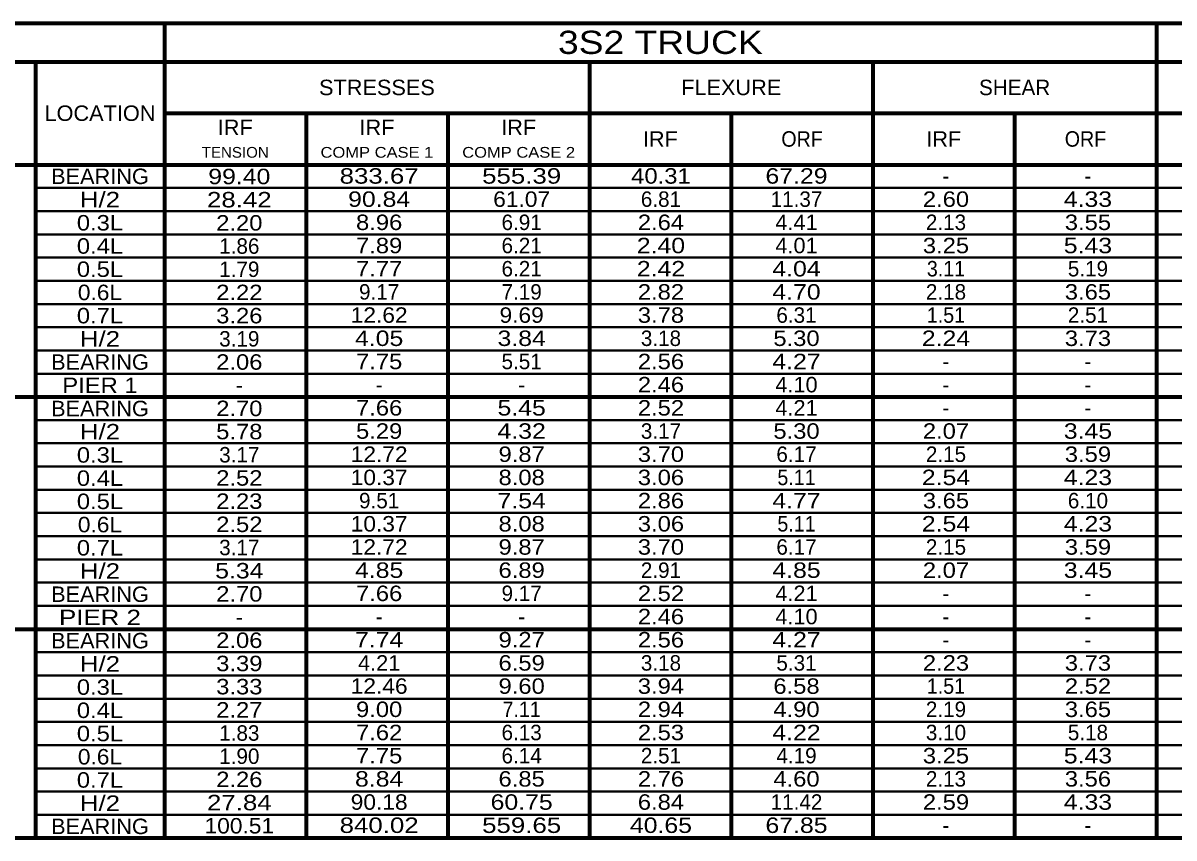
# Model space of a CAD drawing. Extents: x -2055 to -1915, y -81 to 6.
# Drawn here: x -2006.24 to -1961.57, y -66.78 to -35.15 of the extents above; entities that cross this region are included whole.
import ezdxf
from ezdxf.enums import TextEntityAlignment as Align

# ---------------------------------------------------------------- set-up
doc = ezdxf.new("R2010")
doc.units = 0
doc.header["$LTSCALE"] = 0.24
doc.layers.add('1', color=7, linetype='Continuous', lineweight=70)
doc.layers.add('5', color=7, linetype='Continuous', lineweight=40)
doc.layers.add('21', color=7, linetype='Continuous')
doc.layers.add('9', color=7, linetype='Continuous')

msp = doc.modelspace()

# ---------------------------------------------------------------- linework, layer by layer
at = {"layer": '1'}
for p, q in [((-2009.7523, -35.1469), (-1923.7523, -35.1469)), ((-2000.7523, -35.1469), (-2000.7523, -66.7771)), ((-1962.2523, -35.1469), (-1962.2523, -66.7771)), ((-2009.7523, -36.6469), (-1923.7523, -36.6469)), ((-2005.7523, -36.6469), (-2005.7523, -66.7771)), ((-1984.2523, -36.6469), (-1984.2523, -66.7771)), ((-1973.2523, -36.6469), (-1973.2523, -66.7771)), ((-2000.7523, -38.6469), (-1923.7523, -38.6469)), ((-1995.2523, -38.6469), (-1995.2523, -66.7771)), ((-1989.7523, -38.6469), (-1989.7523, -66.7771)), ((-1978.7523, -38.6469), (-1978.7523, -66.7771)), ((-1967.7523, -38.6469), (-1967.7523, -66.7771)), ((-2009.7523, -40.6469), (-1923.7523, -40.6469)), ((-2009.7523, -49.6573), (-1923.7523, -49.6573)), ((-2009.7523, -58.6677), (-1923.7523, -58.6677)), ((-2009.7523, -66.7771), (-1923.7523, -66.7771))]:
    msp.add_line(p, q, dxfattribs=at)
at = {"layer": '5'}
for p, q in [((-2005.7523, -41.5479), (-1923.7523, -41.5479)), ((-2005.7523, -42.449), (-1923.7523, -42.449)), ((-2005.7523, -43.35), (-1923.7523, -43.35)), ((-2005.7523, -44.2511), (-1923.7523, -44.2511)), ((-2005.7523, -45.1521), (-1923.7523, -45.1521)), ((-2005.7523, -46.0532), (-1923.7523, -46.0532)), ((-2005.7523, -46.9542), (-1923.7523, -46.9542)), ((-2005.7523, -47.8552), (-1923.7523, -47.8552)), ((-2005.7523, -48.7563), (-1923.7523, -48.7563)), ((-2005.7523, -50.5583), (-1923.7523, -50.5583)), ((-2005.7523, -51.4594), (-1923.7523, -51.4594)), ((-2005.7523, -52.3604), (-1923.7523, -52.3604)), ((-2005.7523, -53.2615), (-1923.7523, -53.2615)), ((-2005.7523, -54.1625), (-1923.7523, -54.1625)), ((-2005.7523, -55.0636), (-1923.7523, -55.0636)), ((-2005.7523, -55.9646), (-1923.7523, -55.9646)), ((-2005.7523, -56.8657), (-1923.7523, -56.8657)), ((-2005.7523, -57.7667), (-1923.7523, -57.7667)), ((-2005.7523, -59.5688), (-1923.7523, -59.5688)), ((-2005.7523, -60.4698), (-1923.7523, -60.4698)), ((-2005.7523, -61.3708), (-1923.7523, -61.3708)), ((-2005.7523, -62.2719), (-1923.7523, -62.2719)), ((-2005.7523, -63.1729), (-1923.7523, -63.1729)), ((-2005.7523, -64.074), (-1923.7523, -64.074)), ((-2005.7523, -64.975), (-1923.7523, -64.975)), ((-2005.7523, -65.8761), (-1923.7523, -65.8761))]:
    msp.add_line(p, q, dxfattribs=at)

# ---------------------------------------------------------------- texts
at = {"layer": '1'}
for s, width, p in [('BEARING', 1.05, (-2003.252, -41.3974)), ('H/2', 1.25, (-2003.2522, -42.2985)), ('0.3L', 1.15, (-2003.2521, -43.1995)), ('0.4L', 1.15, (-2003.2521, -44.1006)), ('0.5L', 1.15, (-2003.2521, -45.0016)), ('0.6L', 1.1, (-2003.2522, -45.9027)), ('0.7L', 1.15, (-2003.2521, -46.8037)), ('H/2', 1.25, (-2003.2522, -47.7047)), ('BEARING', 1.05, (-2003.252, -48.6058)), ('PIER 1', 1.15, (-2003.2522, -49.5068)), ('BEARING', 1.05, (-2003.252, -50.4078)), ('H/2', 1.25, (-2003.2522, -51.3089)), ('0.3L', 1.15, (-2003.2521, -52.2099)), ('0.4L', 1.15, (-2003.2521, -53.111)), ('0.5L', 1.15, (-2003.2521, -54.012)), ('0.6L', 1.1, (-2003.2522, -54.9131)), ('0.7L', 1.15, (-2003.2521, -55.8141)), ('H/2', 1.25, (-2003.2522, -56.7152)), ('BEARING', 1.05, (-2003.252, -57.6162)), ('PIER 2', 1.25, (-2003.2522, -58.5172)), ('BEARING', 1.05, (-2003.252, -59.4183)), ('H/2', 1.25, (-2003.2522, -60.3193)), ('0.3L', 1.15, (-2003.2521, -61.2203)), ('0.4L', 1.15, (-2003.2521, -62.1214)), ('0.5L', 1.15, (-2003.2521, -63.0224)), ('0.6L', 1.1, (-2003.2522, -63.9235)), ('0.7L', 1.15, (-2003.2521, -64.8245)), ('H/2', 1.25, (-2003.2522, -65.7256)), ('BEARING', 1.05, (-2003.252, -66.6266))]:
    msp.add_text(s, height=0.6, dxfattribs=dict(at, width=width)).set_placement(p, align=Align.CENTER)
at = {"layer": '21'}
for s, height, width, p in [('STRESSES', 0.6, 1.05, (-1992.5022, -37.9469)), ('FLEXURE', 0.6, 1.05, (-1978.7521, -37.9469)), ('LOCATION', 0.6, 1.05, (-2003.2522, -38.9469)), ('IRF', 0.6, 1.05, (-1998.0021, -39.4969)), ('IRF', 0.6, 1.05, (-1992.5021, -39.4969)), ('IRF', 0.6, 1.05, (-1987.0021, -39.4969)), ('IRF', 0.6, 1.05, (-1981.5021, -39.9469)), ('ORF', 0.6, 0.95, (-1976.0022, -39.9469)), ('IRF', 0.6, 1.05, (-1970.5021, -39.9469)), ('ORF', 0.6, 0.95, (-1965.0022, -39.9469)), ('TENSION', 0.4167, 1.05, (-1998.0022, -40.3742)), ('COMP CASE 1', 0.4167, 1.15, (-1992.5022, -40.3742)), ('COMP CASE 2', 0.4167, 1.15, (-1987.0023, -40.3742))]:
    msp.add_text(s, height=height, dxfattribs=dict(at, width=width)).set_placement(p, align=Align.CENTER)
msp.add_text('SHEAR', height=0.6, dxfattribs=at).set_placement((-1967.7522, -37.9469), align=Align.CENTER)
at = {"layer": '9'}
for s, height, width, p in [('3S2 TRUCK', 0.9, 1.2, (-1981.5019, -36.3469)), ('99.40', 0.6, 1.2, (-1997.8438, -41.4031)), ('833.67', 0.6, 1.25, (-1992.4167, -41.3822)), ('555.39', 0.6, 1.25, (-1986.8856, -41.3822)), ('40.31', 0.6, 1.15, (-1981.4792, -41.3822)), ('67.29', 0.6, 1.2, (-1976.2184, -41.3822)), ('28.42', 0.6, 1.25, (-1997.8438, -42.3031)), ('90.84', 0.6, 1.2, (-1992.4168, -42.2822)), ('61.07', 0.6, 1.1, (-1986.8856, -42.2822)), ('2.60', 0.6, 1.15, (-1970.417, -42.2822)), ('4.33', 0.6, 1.2, (-1964.9067, -42.2822)), ('2.20', 0.6, 1.15, (-1997.8438, -43.2031)), ('8.96', 0.6, 1.15, (-1992.4167, -43.1822)), ('2.64', 0.6, 1.15, (-1981.4792, -43.1822)), ('4.41', 0.6, 1.05, (-1976.2184, -43.1822)), ('3.55', 0.6, 1.15, (-1964.9067, -43.1822)), ('7.89', 0.6, 1.15, (-1992.4167, -44.0823)), ('2.40', 0.6, 1.2, (-1981.4792, -44.0823)), ('4.01', 0.6, 1.05, (-1976.2184, -44.0823)), ('3.25', 0.6, 1.15, (-1970.417, -44.0823)), ('5.43', 0.6, 1.2, (-1964.9067, -44.0823)), ('7.77', 0.6, 1.15, (-1992.4167, -44.9823)), ('2.42', 0.6, 1.2, (-1981.4793, -44.9823)), ('4.04', 0.6, 1.2, (-1976.2184, -44.9823)), ('3.11', 0.6, 0.95, (-1970.417, -44.9823)), ('2.22', 0.6, 1.15, (-1997.8438, -45.9031)), ('2.82', 0.6, 1.15, (-1981.4793, -45.8822)), ('4.70', 0.6, 1.2, (-1976.2184, -45.8822)), ('3.65', 0.6, 1.15, (-1964.9067, -45.8822)), ('3.26', 0.6, 1.15, (-1997.8439, -46.8031)), ('12.62', 0.6, 1.1, (-1992.4167, -46.7822)), ('9.69', 0.6, 1.1, (-1986.8855, -46.7822)), ('3.78', 0.6, 1.15, (-1981.4793, -46.7822)), ('1.51', 0.6, 0.95, (-1970.417, -46.7822)), ('4.05', 0.6, 1.2, (-1992.4167, -47.6822)), ('3.84', 0.6, 1.2, (-1986.8856, -47.6822)), ('5.30', 0.6, 1.15, (-1976.2184, -47.6822)), ('2.24', 0.6, 1.2, (-1970.417, -47.6822)), ('3.73', 0.6, 1.15, (-1964.9067, -47.6822)), ('2.06', 0.6, 1.15, (-1997.8438, -48.6031)), ('7.75', 0.6, 1.15, (-1992.4167, -48.5822)), ('2.56', 0.6, 1.15, (-1981.4793, -48.5822)), ('4.27', 0.6, 1.2, (-1976.2185, -48.5822)), ('2.46', 0.6, 1.15, (-1981.4793, -49.4823)), ('4.10', 0.6, 1.05, (-1976.2184, -49.4823)), ('2.70', 0.6, 1.15, (-1997.8438, -50.4031)), ('7.66', 0.6, 1.15, (-1992.4167, -50.3822)), ('5.45', 0.6, 1.2, (-1986.8856, -50.3822)), ('2.52', 0.6, 1.15, (-1981.4793, -50.3822)), ('4.21', 0.6, 1.05, (-1976.2185, -50.3822)), ('5.78', 0.6, 1.15, (-1997.8438, -51.3031)), ('5.29', 0.6, 1.15, (-1992.4168, -51.2822)), ('4.32', 0.6, 1.2, (-1986.8856, -51.2822)), ('5.30', 0.6, 1.15, (-1976.2184, -51.2822)), ('2.07', 0.6, 1.15, (-1970.417, -51.2822)), ('3.45', 0.6, 1.2, (-1964.9067, -51.2822)), ('12.72', 0.6, 1.1, (-1992.4167, -52.1822)), ('9.87', 0.6, 1.15, (-1986.8856, -52.1822)), ('3.70', 0.6, 1.15, (-1981.4792, -52.1822)), ('3.59', 0.6, 1.15, (-1964.9067, -52.1822)), ('2.52', 0.6, 1.15, (-1997.8438, -53.1031)), ('10.37', 0.6, 1.1, (-1992.4167, -53.0822)), ('8.08', 0.6, 1.15, (-1986.8856, -53.0822)), ('3.06', 0.6, 1.15, (-1981.4792, -53.0822)), ('5.11', 0.6, 0.95, (-1976.2184, -53.0822)), ('2.54', 0.6, 1.2, (-1970.417, -53.0822)), ('4.23', 0.6, 1.2, (-1964.9067, -53.0822)), ('2.23', 0.6, 1.15, (-1997.8438, -54.0031)), ('7.54', 0.6, 1.2, (-1986.8856, -53.9823)), ('2.86', 0.6, 1.15, (-1981.4793, -53.9823)), ('4.77', 0.6, 1.2, (-1976.2185, -53.9823)), ('3.65', 0.6, 1.15, (-1970.417, -53.9823)), ('2.52', 0.6, 1.15, (-1997.8438, -54.9031)), ('10.37', 0.6, 1.1, (-1992.4167, -54.8822)), ('8.08', 0.6, 1.15, (-1986.8856, -54.8822)), ('3.06', 0.6, 1.15, (-1981.4792, -54.8822)), ('5.11', 0.6, 0.95, (-1976.2184, -54.8822)), ('2.54', 0.6, 1.2, (-1970.417, -54.8822)), ('4.23', 0.6, 1.2, (-1964.9067, -54.8822)), ('12.72', 0.6, 1.1, (-1992.4167, -55.7822)), ('9.87', 0.6, 1.15, (-1986.8856, -55.7822)), ('3.70', 0.6, 1.15, (-1981.4792, -55.7822)), ('3.59', 0.6, 1.15, (-1964.9067, -55.7822)), ('5.34', 0.6, 1.2, (-1997.8438, -56.7031)), ('4.85', 0.6, 1.2, (-1992.4167, -56.6822)), ('6.89', 0.6, 1.15, (-1986.8856, -56.6822)), ('4.85', 0.6, 1.2, (-1976.2185, -56.6822)), ('2.07', 0.6, 1.15, (-1970.417, -56.6822)), ('3.45', 0.6, 1.2, (-1964.9067, -56.6822)), ('2.70', 0.6, 1.15, (-1997.8438, -57.6031)), ('7.66', 0.6, 1.15, (-1992.4167, -57.5822)), ('2.52', 0.6, 1.15, (-1981.4793, -57.5822)), ('4.21', 0.6, 1.05, (-1976.2185, -57.5822)), ('2.46', 0.6, 1.15, (-1981.4793, -58.4823)), ('4.10', 0.6, 1.05, (-1976.2184, -58.4823)), ('2.06', 0.6, 1.15, (-1997.8438, -59.4031)), ('7.74', 0.6, 1.2, (-1992.4167, -59.3822)), ('9.27', 0.6, 1.15, (-1986.8856, -59.3822)), ('2.56', 0.6, 1.15, (-1981.4793, -59.3822)), ('4.27', 0.6, 1.2, (-1976.2185, -59.3822)), ('3.39', 0.6, 1.15, (-1997.8439, -60.3031)), ('4.21', 0.6, 1.05, (-1992.4167, -60.2822)), ('6.59', 0.6, 1.15, (-1986.8856, -60.2822)), ('2.23', 0.6, 1.15, (-1970.417, -60.2822)), ('3.73', 0.6, 1.15, (-1964.9067, -60.2822)), ('3.33', 0.6, 1.15, (-1997.8438, -61.2031)), ('12.46', 0.6, 1.1, (-1992.4167, -61.1822)), ('9.60', 0.6, 1.15, (-1986.8856, -61.1822)), ('3.94', 0.6, 1.15, (-1981.4792, -61.1822)), ('6.58', 0.6, 1.15, (-1976.2184, -61.1822)), ('1.51', 0.6, 0.95, (-1970.417, -61.1822)), ('2.52', 0.6, 1.15, (-1964.9067, -61.1822)), ('2.27', 0.6, 1.15, (-1997.8438, -62.1031)), ('9.00', 0.6, 1.15, (-1992.4167, -62.0822)), ('7.11', 0.6, 0.95, (-1986.8856, -62.0822)), ('2.94', 0.6, 1.15, (-1981.4792, -62.0822)), ('4.90', 0.6, 1.15, (-1976.2185, -62.0822)), ('3.65', 0.6, 1.15, (-1964.9067, -62.0822)), ('7.62', 0.6, 1.15, (-1992.4167, -62.9823)), ('2.53', 0.6, 1.15, (-1981.4793, -62.9823)), ('4.22', 0.6, 1.2, (-1976.2185, -62.9823)), ('7.75', 0.6, 1.15, (-1992.4167, -63.8822)), ('3.25', 0.6, 1.15, (-1970.417, -63.8822)), ('5.43', 0.6, 1.2, (-1964.9067, -63.8822)), ('2.26', 0.6, 1.15, (-1997.8439, -64.8031)), ('8.84', 0.6, 1.2, (-1992.4167, -64.7823)), ('6.85', 0.6, 1.15, (-1986.8856, -64.7823)), ('2.76', 0.6, 1.15, (-1981.4793, -64.7823)), ('4.60', 0.6, 1.15, (-1976.2185, -64.7823)), ('3.56', 0.6, 1.15, (-1964.9067, -64.7823)), ('27.84', 0.6, 1.25, (-1997.8438, -65.7031)), ('90.18', 0.6, 1.1, (-1992.4167, -65.6822)), ('60.75', 0.6, 1.2, (-1986.8856, -65.6822)), ('6.84', 0.6, 1.15, (-1981.4792, -65.6822)), ('2.59', 0.6, 1.15, (-1970.417, -65.6822)), ('4.33', 0.6, 1.2, (-1964.9067, -65.6822)), ('100.51', 0.6, 1.1, (-1997.8438, -66.6031)), ('840.02', 0.6, 1.25, (-1992.4168, -66.5823)), ('559.65', 0.6, 1.25, (-1986.8856, -66.5823)), ('40.65', 0.6, 1.2, (-1981.4793, -66.5823)), ('67.85', 0.6, 1.2, (-1976.2184, -66.5823))]:
    msp.add_text(s, height=height, dxfattribs=dict(at, width=width)).set_placement(p, align=Align.CENTER)
for s, p in [('-', (-1970.417, -41.3822)), ('-', (-1964.9067, -41.3822)), ('6.81', (-1981.4792, -42.2822)), ('11.37', (-1976.2184, -42.2822)), ('6.91', (-1986.8856, -43.1822)), ('2.13', (-1970.417, -43.1822)), ('1.86', (-1997.8438, -44.1031)), ('6.21', (-1986.8856, -44.0823)), ('1.79', (-1997.8438, -45.0031)), ('6.21', (-1986.8856, -44.9823)), ('5.19', (-1964.9067, -44.9823)), ('9.17', (-1992.4167, -45.8822)), ('7.19', (-1986.8856, -45.8822)), ('2.18', (-1970.417, -45.8822)), ('6.31', (-1976.2184, -46.7822)), ('2.51', (-1964.9067, -46.7822)), ('3.19', (-1997.8438, -47.7031)), ('3.18', (-1981.4792, -47.6822)), ('5.51', (-1986.8856, -48.5822)), ('-', (-1970.417, -48.5822)), ('-', (-1964.9067, -48.5822)), ('-', (-1997.8438, -49.5031)), ('-', (-1992.4167, -49.4823)), ('-', (-1986.8856, -49.4823)), ('-', (-1970.417, -49.4823)), ('-', (-1964.9067, -49.4823)), ('-', (-1970.417, -50.3822)), ('-', (-1964.9067, -50.3822)), ('3.17', (-1981.4792, -51.2822)), ('3.17', (-1997.8438, -52.2031)), ('6.17', (-1976.2184, -52.1822)), ('2.15', (-1970.417, -52.1822)), ('9.51', (-1992.4167, -53.9823)), ('6.10', (-1964.9067, -53.9823)), ('3.17', (-1997.8438, -55.8031)), ('6.17', (-1976.2184, -55.7822)), ('2.15', (-1970.417, -55.7822)), ('2.91', (-1981.4792, -56.6822)), ('9.17', (-1986.8855, -57.5822)), ('-', (-1970.417, -57.5822)), ('-', (-1964.9067, -57.5822)), ('-', (-1997.8438, -58.5031)), ('-', (-1992.4167, -58.4823)), ('-', (-1986.8856, -58.4823)), ('-', (-1970.417, -58.4823)), ('-', (-1964.9067, -58.4823)), ('-', (-1970.417, -59.3822)), ('-', (-1964.9067, -59.3822)), ('3.18', (-1981.4792, -60.2822)), ('5.31', (-1976.2185, -60.2822)), ('2.19', (-1970.417, -62.0822)), ('1.83', (-1997.8438, -63.0031)), ('6.13', (-1986.8856, -62.9823)), ('3.10', (-1970.417, -62.9823)), ('5.18', (-1964.9067, -62.9823)), ('1.90', (-1997.8438, -63.9031)), ('6.14', (-1986.8855, -63.8822)), ('2.51', (-1981.4792, -63.8822)), ('4.19', (-1976.2185, -63.8822)), ('2.13', (-1970.417, -64.7823)), ('11.42', (-1976.2184, -65.6822)), ('-', (-1970.417, -66.5823)), ('-', (-1964.9067, -66.5823))]:
    msp.add_text(s, height=0.6, dxfattribs=at).set_placement(p, align=Align.CENTER)

doc.saveas('drawing.dxf')
